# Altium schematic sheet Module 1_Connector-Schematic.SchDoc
size A4; DocumentNumber: 3; SheetNumber: 3; SheetTotal: 5; PageSetup: Record=PageOptions¦CenterHorizontal=True¦CenterVertical=True¦PrintScale=0.73¦XCorrection=1.00¦YCorrection=1.00¦PrintKind=0¦BorderSize=5000000¦LeftOffset=0¦BottomOffset=0¦Orientation=2¦PaperLength=1000¦PaperWidth=1000¦Scale=100¦PaperSource=7¦PrintQuality=-3¦MediaType=1¦DitherType=10¦PrintScaleMode=1¦PaperKind=A4¦PaperIndex=9
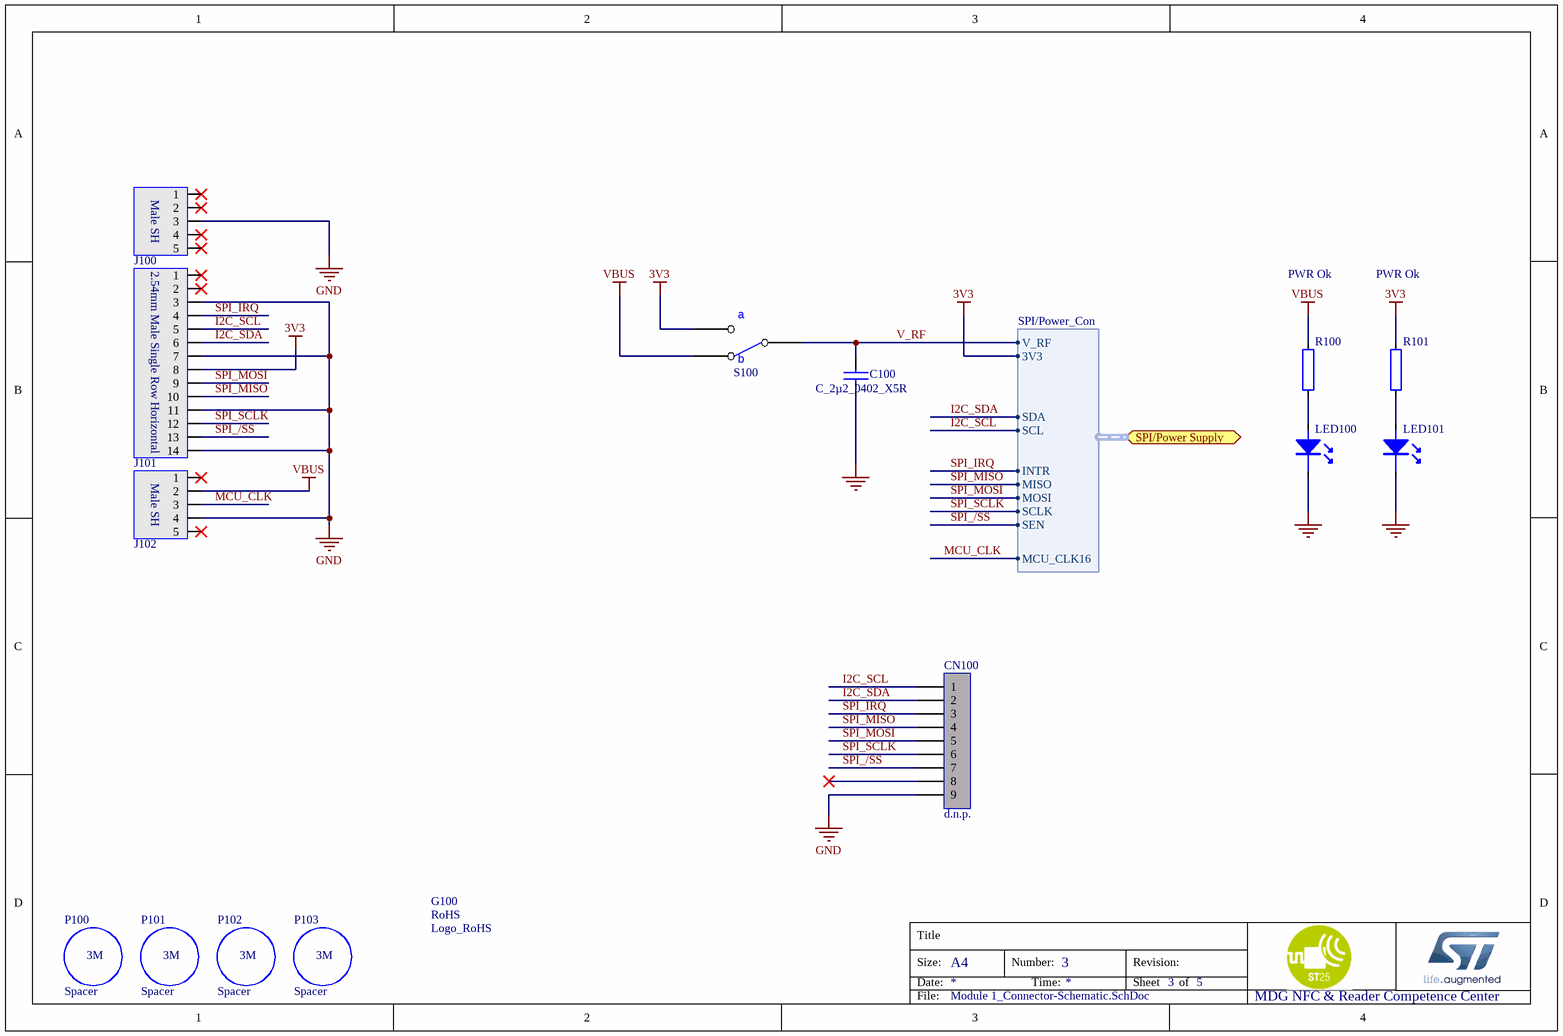
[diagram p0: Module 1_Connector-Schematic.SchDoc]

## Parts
C100  C_2µ2_0402_X5R  [C0402]
CN100  d.n.p.  [1*9P_MALE]  (no BOM)
G100  Logo_RoHS  [Logo_RoHS_CHN]
J100  Male Single Row Horizontal  [TSW-105-08-G-S-NA]  (value not drawn)
J101  Male Single Row Horizontal  [TSW-114-08-G-S-NA]  (value not drawn)
J102  Male Single Row Horizontal  [TSW-105-08-G-S-NA]  (value not drawn)
LED100  Green  [D0603]  (value not drawn)
LED101  Green  [D0603]  (value not drawn)
P100  Spacer  [spacer]
P101  Spacer  [spacer]
P102  Spacer  [spacer]
P103  Spacer  [spacer]
R100  1k  [R0402]  (value not drawn)
R101  680R  [R0402]  (value not drawn)
S100  PCM12SMTR  [SW_PCM12SMTR]  (value not drawn)

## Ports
SPI/Power Supply (harness SPI/Power_Con)

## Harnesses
SPI/Power_Con: SEN, INTR, MISO, MOSI, SCLK, V_RF, 3V3, SDA, SCL, MCU_CLK16

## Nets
3V3: J101.8 R101.2 S100.1 ; port SPI/Power Supply.3V3
GND: C100.2 CN100.9 J100.3 J101.3 J101.7 J101.11 J101.14 J102.4 LED100.2 LED101.2
VBUS: J102.2 R100.2 S100.3
I2C_SCL: CN100.1 J101.5 ; port SPI/Power Supply.SCL
I2C_SDA: CN100.2 J101.6 ; port SPI/Power Supply.SDA
MCU_CLK: J102.3 ; port SPI/Power Supply.MCU_CLK16
SPI_/SS: CN100.7 J101.13 ; port SPI/Power Supply.SEN
SPI_IRQ: CN100.3 J101.4 ; port SPI/Power Supply.INTR
SPI_MISO: CN100.4 J101.10 ; port SPI/Power Supply.MISO
SPI_MOSI: CN100.5 J101.9 ; port SPI/Power Supply.MOSI
SPI_SCLK: CN100.6 J101.12 ; port SPI/Power Supply.SCLK
V_RF: C100.1 S100.2 ; port SPI/Power Supply.V_RF
NetLED100_1: LED100.1 R100.1
NetLED101_1: LED101.1 R101.1

Not connected (* = marked no-connect by the designer): CN100 8*; J100 1* 2* 4* 5*; J101 1* 2*; J102 1* 5*

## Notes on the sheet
- PWR Ok

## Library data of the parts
C100 = C_2µ2_0402_X5R: 2u2_X5R; Manufacturer: MURATA; Manufacturer Part Number: GRM155R60J225ME15D; 2nd Source: 0402, 2.2 µF, 6.3 V, ± 20%, X5R
CN100 = Header 9X1_Female: Manufacturer: Samtec; Manufacturer Part Number: SSQ-107-03-L-S; Comments: RECEPTACLE, 2.54MM, SINGLE ROW, 7WAY; 2nd source: doublesourcing allowed
J100 J102 = TSW-105-08-G-S-NA: Male Single Row Horizontal 5 pin; Manufacturer: Samtec; 2nd Source: doublesourcing allowed
J101 = TSW-114-08-G-S-NA: Male Single Row Horizontal 14 pin; Manufacturer: Samtec; 2nd Source: doublesourcing allowed
LED100 LED101 = LED-0603-Green: Manufacturer: Lite-On; Manufacturer Part Number: LTST-C190KGKT
P100-P103 = Spacer: Samtec; Manufacturer: 3M; Manufacturer Part Number: SJ5303TRANS; 2nd Source: doublesourcing allowed
R100 = R0402_1k: 1k, 0402; Manufacturer: Panasonic; Manufacturer Part Number: ERJ2GEJ102X; 2nd Source: 1 kohm, 50 V, 0402, >100 mW, ± 5%
R101 = R0402_680R: 680R, 0402; Manufacturer: Yageo; Manufacturer Part Number: RC0402JR-07680RL; 2nd Source: 680 Ohm ±5% 0.063W, 1/16W Chip Resistor 0402
S100 = SW_DPST1_THMD: Manufacturer: C & K COMPONENTS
